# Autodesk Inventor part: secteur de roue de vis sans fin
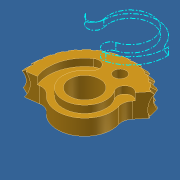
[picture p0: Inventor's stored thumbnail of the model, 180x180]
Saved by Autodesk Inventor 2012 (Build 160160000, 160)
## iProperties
Created: 2011-10
Part Number: secteur de roue de vis sans fin
Material: Laiton (jaune doux)
Document SubType Name: Modeling
Designer: Laur
Mass: 5.8954 g
Surface Area: 7.57262 cm^2
Volume: 0.696033 cm^3
Density: 8.47 g/cm^3
Author: Laur
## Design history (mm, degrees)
derived "secteur roue de vis sans fin.iam"
sketch "Esquisse2"
  geometry: L1 (-10.467, -29.707)-(10.078, 28.605) reference; L2 (-5.666, -0.387)-(-9.988, 0.485); L3 (5.478, 1.496)-(9.274, 3.74); A1 r 7.753 centre (0, 0) between (2.119, 7.458) and (1.097, 7.675) reference; A2 r 1.5 centre (0, 0) between (-0.498, -1.415) and (0.498, 1.415); A3 r 1.5 centre (0, 0) between (-0.297, -1.47) and (0.763, -1.291); A4 r 10 centre (0, 0) between (-9.988, 0.485) and (9.274, 3.74); A5 r 7.753 centre (0, 0) between (3.623, 6.854) and (2.669, 7.279) reference; A6 r 4.5 centre (0, 0) between (-4.196, -1.625) and (4.497, -0.156); A7 r 2 centre (-6.061, -2.347) between (-4.196, -1.625) and (-5.666, -0.387); A8 r 2 centre (6.496, -0.225) between (5.478, 1.496) and (4.497, -0.156)
  constraints: 14 point on circle, 7 tangent, 6 centre point, 4 coincident, 4 end point, 4 point on line, 1 equal radius
  dimensions: "d4" = 3 diameter of A2; "d5" = 138 deg angle of L3 L2; "d6" = 40 deg angle of L3 L1; "d7" = 10 radius of A4; "d10" = 4.5 radius of A6; "d11" = 2 radius of A7
extrude "découpe secteur 13 dents complètes" cut sketch "Esquisse2" stored distance "d8" = 10; taper "d9" = 0 deg
sketch "Esquisse3"
  geometry: L1 (1.443, 5.492)-(1.421, 7.622) reference; L2 (0, 0)-(-4.628, 8.15); C1 r 2.5 at (0, 0); C2 r 1 at (-2.469, 4.348); A1 r 7.753 centre (0, 0) between (1.421, 7.622) and (1.097, 7.675) reference; A2 r 7.753 centre (0, 0) between (-4.969, -5.951) and (-4.124, -6.565) reference
  constraints: 2 centre point, 2 end point, 1 coincident, 1 point on line
  dimensions: "d12" = 29 deg angle of L1 L2; "d13" = 2 diameter of C2; "d14" = 5 distance of A1.centre C2.centre; "d15" = 5 diameter of C1
extrude "alésage arbre et alésage capteur angulaire" cut sketch "Esquisse3" stored distance "d16" = 10; taper "d17" = 0 deg
sketch "Esquisse4"
  geometry: L1 (1.443, 5.492)-(1.421, 7.622) reference; L2 (0, 0)-(-0.074, 7.137); L3 (0, 0)-(-10.241, 5.772); A1 r 7.753 centre (0, 0) between (-4.969, -5.951) and (-4.124, -6.565) reference; A2 r 6 centre (0, 0) between (-5.808, 1.507) and (1.44, 5.825); A3 r 3.55 centre (0, 0) between (-3.436, 0.891) and (0.875, 3.44); A4 r 1.225 centre (-4.622, 1.199) between (-3.436, 0.891) and (-5.808, 1.507); A5 r 1.225 centre (1.177, 4.628) between (1.479, 5.815) and (0.875, 3.44)
  constraints: 9 point on circle, 6 tangent, 4 centre point, 4 end point, 2 coincident, 1 parallel, 1 point on line
  dimensions: "d18" = 60 deg angle of L2 L3; "d19" = 7.1 diameter of A3; "d21" = 12 diameter of A2
extrude "Extrusion3" cut sketch "Esquisse4" distance "d22" = 1.2; taper "d23" = 0 deg
sketch "Esquisse5"
  geometry: L1 (5.539, -1.251)-(7.667, -1.155) reference; L2 (-6.76, 3.613)-(-5.184, 2.318) reference; L3 (0, 0)-(4.908, 14.746); C1 r 2.5 at (0, 0) reference; C2 r 1 at (-1.84, 4.649) reference; A1 r 7.753 centre (0, 0) between (7.667, -1.155) and (7.675, -1.097) reference; A2 r 7.753 centre (0, 0) between (7.736, -0.522) and (7.736, 0.522) reference; A3 r 7.753 centre (0, 0) between (7.675, 1.097) and (7.458, 2.119) reference; A4 r 7.753 centre (0, 0) between (7.279, 2.669) and (6.854, 3.623) reference; A5 r 7.753 centre (0, 0) between (6.565, 4.124) and (5.951, 4.969) reference; A6 r 7.753 centre (0, 0) between (5.564, 5.399) and (4.788, 6.098) reference; A7 r 7.753 centre (0, 0) between (4.32, 6.438) and (3.415, 6.96) reference; A8 r 7.753 centre (0, 0) between (2.887, 7.195) and (1.894, 7.518) reference; A9 r 7.753 centre (0, 0) between (1.328, 7.639) and (0.289, 7.748) reference; A10 r 7.753 centre (0, 0) between (-0.289, 7.748) and (-1.328, 7.639) reference; A11 r 7.753 centre (0, 0) between (-1.894, 7.518) and (-2.887, 7.195) reference; A12 r 7.753 centre (0, 0) between (-3.415, 6.96) and (-4.32, 6.438) reference; A13 r 7.753 centre (0, 0) between (-4.788, 6.098) and (-5.564, 5.399) reference; A14 r 7.753 centre (0, 0) between (-5.951, 4.969) and (-6.565, 4.124) reference; A15 r 2 centre (-6.454, 0.773) between (-4.468, 0.535) and (-5.184, 2.318) reference; A16 r 4.5 centre (0, 0) between (-4.468, 0.535) and (3.898, -2.249) reference; A17 r 2 centre (5.63, -3.249) between (5.539, -1.251) and (3.898, -2.249) reference; 41 further points; 14 other entities
  constraints: 2 end point, 41 other
  dimensions: "d24" = 138 deg angle of L1 L2 (derived); "d25" = 69 deg angle of L1 L3 (= 0.5 x d24)
node "Solide1"
node "Corps solides"
node "Corps surfaciques"
node "secteur-roue de sortie.ipt:1"
node "Engrenages à vis sans fin:1::Engrenage à vis sans fin:1"
